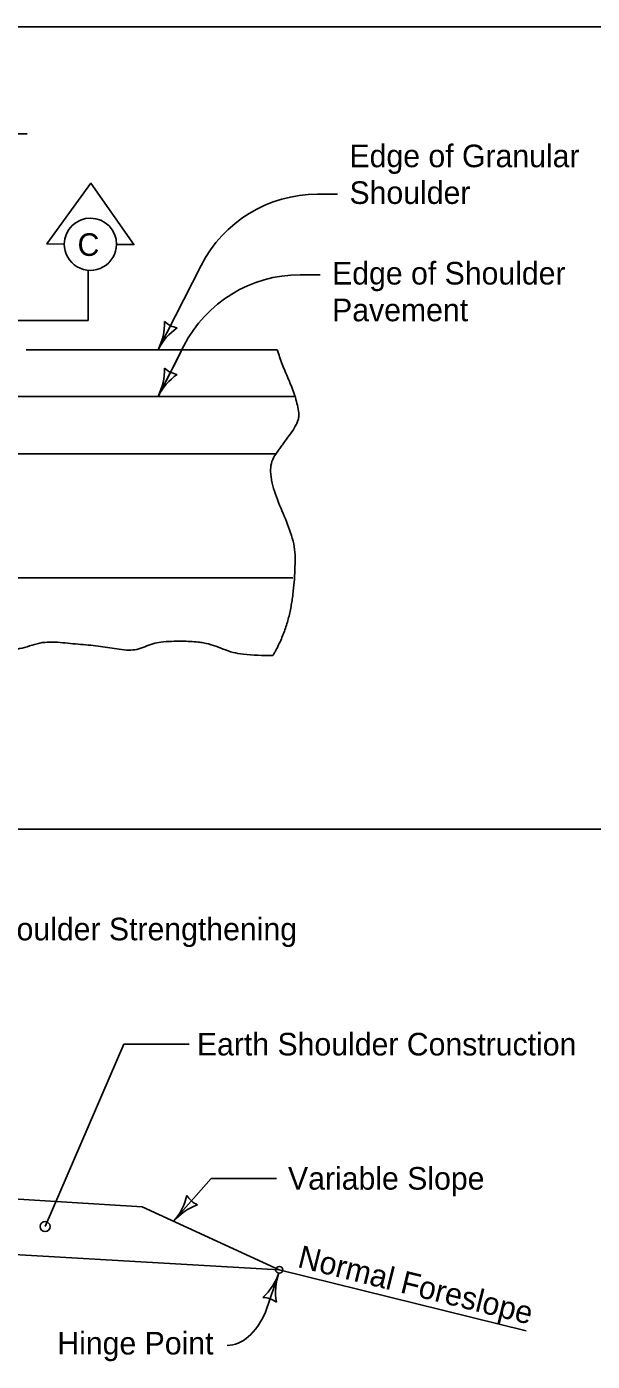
# Model space of a CAD drawing. Extents: x 6410 to 81668, y 3928 to 11667.
# Drawn here: x 8064 to 8465, y 8980 to 9924 of the extents above; entities that cross this region are included whole.
import ezdxf

# ---------------------------------------------------------------- set-up
doc = ezdxf.new("R2010")
doc.units = 0
for name, color, linetype in [('dsnCellElements', 7, 'Continuous'), ('dsnNonPlotable', 7, 'Continuous'), ('dsnShtPlotShapeBatchPrint', 7, 'Continuous'), ('dsnStdBlockModified', 7, 'Continuous'), ('dsnStdSection', 7, 'Continuous'), ('Level 10', 7, 'Continuous'), ('Level 11', 7, 'Continuous'), ('Level 14', 7, 'Continuous')]:
    doc.layers.add(name, color=color, linetype=linetype)

msp = doc.modelspace()

# ---------------------------------------------------------------- linework, layer by layer
at = {"layer": 'dsnCellElements'}
for p, q in [((8270.07, 9805.77), (8284.37, 9805.77)), ((8270.07, 9805.77), (8284.37, 9805.77)), ((8187.76, 9755.4), (8157.22, 9695.63)), ((8187.76, 9755.4), (8157.22, 9695.63)), ((8257.76, 9748.71), (8272.07, 9748.71)), ((8257.76, 9748.71), (8272.07, 9748.71)), ((8175.45, 9698.33), (8157.22, 9662.65)), ((8175.45, 9698.33), (8157.22, 9662.65))]:
    msp.add_line(p, q, dxfattribs=at)
for centre, radius, start, end in [((8270.07, 9713.34), 92.43, 90, 152.9341), ((8270.07, 9713.34), 92.43, 90, 152.9341), ((8257.76, 9656.28), 92.43, 90, 152.9341), ((8257.76, 9656.28), 92.43, 90, 152.9341), ((8119.37, 9714.97), 42.5, 332.9341, 1.00659), ((8119.37, 9714.97), 42.5, 332.9341, 1.00659), ((8173.44, 9727.37), 16.42, 225.20075, 260.66745), ((8173.44, 9727.37), 16.42, 225.20075, 260.66745), ((8195.07, 9676.3), 42.5, 124.86161, 152.9341), ((8195.07, 9676.3), 42.5, 124.86161, 152.9341), ((8119.37, 9681.99), 42.5, 332.9341, 1.00659), ((8119.37, 9681.99), 42.5, 332.9341, 1.00659), ((8195.07, 9643.32), 42.5, 124.86161, 152.9341), ((8195.07, 9643.32), 42.5, 124.86161, 152.9341), ((8173.44, 9694.39), 16.42, 225.20075, 260.66745), ((8173.44, 9694.39), 16.42, 225.20075, 260.66745)]:
    msp.add_arc(centre, radius, start, end, dxfattribs=at)
at = {"layer": 'dsnNonPlotable'}
msp.add_line((6410.45, 9924.36), (9506.14, 9924.36), dxfattribs=at)
at = {"layer": 'dsnShtPlotShapeBatchPrint'}
msp.add_line((7928.55, 9848.49), (8064.55, 9848.49), dxfattribs=at)
msp.add_line((7928.55, 9848.49), (8064.55, 9848.49), dxfattribs=at)
at = {"layer": 'dsnStdBlockModified'}
for p, q in [((8063.76, 9695.63), (8241.65, 9695.63)), ((8173.47, 9694.45), (8157.22, 9662.65)), ((6605.92, 9662.65), (8253.39, 9662.65)), ((6627.13, 9622), (8240.92, 9622)), ((8011.25, 9097.23), (8146.01, 9088.85)), ((8146.01, 9088.85), (8243.06, 9044.35)), ((8243.06, 9044.35), (7666.95, 9077.58)), ((8243.06, 9044.35), (8418.04, 9001.05))]:
    msp.add_line(p, q, dxfattribs=at)
msp.add_ellipse((8243.06, 9044.35), major_axis=(2.58, 0), ratio=0.913811, dxfattribs=at)
for points in [[(8241.65, 9695.63), (8245.11, 9685.5), (8249.47, 9675.11), (8253.63, 9664.48), (8255.28, 9659.07), (8256.46, 9653.6), (8256.84, 9648.22), (8256.64, 9646.85), (8256.31, 9645.5), (8255.2, 9642.92), (8248.27, 9632.42), (8246.36, 9629.77), (8244.41, 9627.15), (8242.46, 9624.53), (8240.56, 9621.86), (8237.92, 9616.48), (8236.91, 9611), (8237.12, 9607.14), (8237.68, 9603.28), (8239.69, 9595.51), (8245.75, 9579.86), (8251.75, 9564.14), (8253.67, 9556.28), (8254.33, 9548.45), (8254.1, 9539.85), (8253.62, 9531.2), (8252.74, 9522.48), (8252.12, 9518.13), (8251.4, 9513.8), (8249.42, 9505), (8246.69, 9496.4), (8243.1, 9487.76), (8240.94, 9483.46), (8239.77, 9481.31), (8238.52, 9479.17)], [(7958.81, 9482.92), (7960.81, 9483.03), (7968.39, 9483.51), (7975.95, 9484.17), (7983.5, 9484.98), (7991.04, 9485.88), (7995.78, 9486.88), (8000.47, 9488.32), (8005.14, 9489.68), (8007.49, 9490.17), (8009.85, 9490.44), (8016.39, 9490.43), (8022.98, 9489.77), (8029.57, 9488.74), (8036.08, 9487.59), (8040.09, 9486.65), (8044.07, 9485.45), (8048.04, 9484.32), (8052.05, 9483.6), (8055.6, 9483.57), (8059.15, 9484.07), (8066.25, 9486), (8073.39, 9488.01), (8080.56, 9488.73), (8095.1, 9487.76), (8109.64, 9486.45), (8116.36, 9485.63), (8123.07, 9484.64), (8129.76, 9483.7), (8136.44, 9483.03), (8142.2, 9483.59), (8147.87, 9485.42), (8153.54, 9487.47), (8159.25, 9488.73), (8166.75, 9489.24), (8174.36, 9489.37), (8185.74, 9488.67), (8189.48, 9488.16), (8196.5, 9486.34), (8203.39, 9483.78), (8210.31, 9481.41), (8217.42, 9480.18), (8238.52, 9479.17)]]:
    msp.add_spline(points, degree=3, dxfattribs=at)
at = {"layer": 'dsnStdSection'}
for p, q in [((8077.18, 9074.96), (8132.9, 9204.09)), ((8132.9, 9204.09), (8179.26, 9204.09)), ((8168.19, 9078.68), (8194.79, 9109.1)), ((8194.79, 9109.1), (8241.15, 9109.1)), ((8233.3, 9014.44), (8242.76, 9042.01))]:
    msp.add_line(p, q, dxfattribs=at)
for centre, radius, start, end in [((8136.19, 9106.64), 42.5, 318.84535, 346.91784), ((8200.19, 9050.71), 42.5, 110.77286, 138.84535), ((8191.64, 9105.51), 16.42, 211.112, 246.5787), ((8202.57, 9055.81), 42.5, 312.97879, 341.05128), ((8282.96, 9028.21), 42.5, 161.05128, 189.12377), ((8231.19, 9008.31), 16.42, 53.31793, 88.78463)]:
    msp.add_arc(centre, radius, start, end, dxfattribs=at)
msp.add_ellipse((8206.21, 9052.29), major_axis=(0, 61.47), ratio=0.559383, start_param=3.141593, end_param=4.048985, dxfattribs=at)
at = {"layer": 'Level 10'}
for p, q in [((8107.82, 9716.47), (8107.82, 9751.91)), ((8107.82, 9716.47), (8107.82, 9751.91)), ((8019.71, 9716.47), (8107.82, 9716.47)), ((8019.71, 9716.47), (8107.82, 9716.47))]:
    msp.add_line(p, q, dxfattribs=at)
msp.add_lwpolyline([(8127.78, 9770.18), (8140.11, 9770.07), (8109.69, 9813.48), (8078.49, 9770.63), (8090.81, 9770.52)], dxfattribs=at)
for start, end in [(359.4792, 179.47754), (179.47754, 359.4792)]:
    msp.add_arc((8109.3, 9770.35), 18.49, start, end, dxfattribs=at)
at = {"layer": 'Level 11'}
for p, q in [((6610.53, 9534.09), (8252.57, 9534.09)), ((8566.03, 9356.36), (6410.45, 9356.36))]:
    msp.add_line(p, q, dxfattribs=at)
at = {"layer": 'Level 14'}
msp.add_circle((8077.18, 9074.96), 3.54, dxfattribs=at)
msp.add_circle((8077.18, 9074.96), 3.54, dxfattribs=at)

# ---------------------------------------------------------------- texts
at = {"layer": 'dsnCellElements'}
for s, p in [('Edge of Granular', (8292.81, 9824.89)), ('Edge of Granular', (8292.81, 9824.89)), ('Shoulder', (8292.81, 9798.89)), ('Shoulder', (8292.81, 9798.89)), ('Edge of Shoulder', (8280.5, 9741.83)), ('Edge of Shoulder', (8280.5, 9741.83)), ('Pavement', (8280.5, 9715.83)), ('Pavement', (8280.5, 9715.83))]:
    msp.add_text(s, height=16, dxfattribs=at).set_placement(p)
at = {"layer": 'dsnStdSection'}
for s, p in [('Edge of Shoulder Strengthening', (7951.12, 9277.59)), ('Earth Shoulder Construction', (8184.73, 9196.09)), ('Variable Slope', (8249.26, 9101.1)), ('Hinge Point', (8085.87, 8984.4))]:
    msp.add_text(s, height=16, dxfattribs=at).set_placement(p)
msp.add_text('Normal Foreslope', height=16, rotation=346.0988, dxfattribs=at).set_placement((8255.31, 9046.4))
at = {"layer": 'Level 10'}
msp.add_text('C', height=16, dxfattribs=at).set_placement((8100.19, 9762.12))
msp.add_text('C', height=16, dxfattribs=at).set_placement((8100.19, 9762.12))

doc.saveas('drawing.dxf')
